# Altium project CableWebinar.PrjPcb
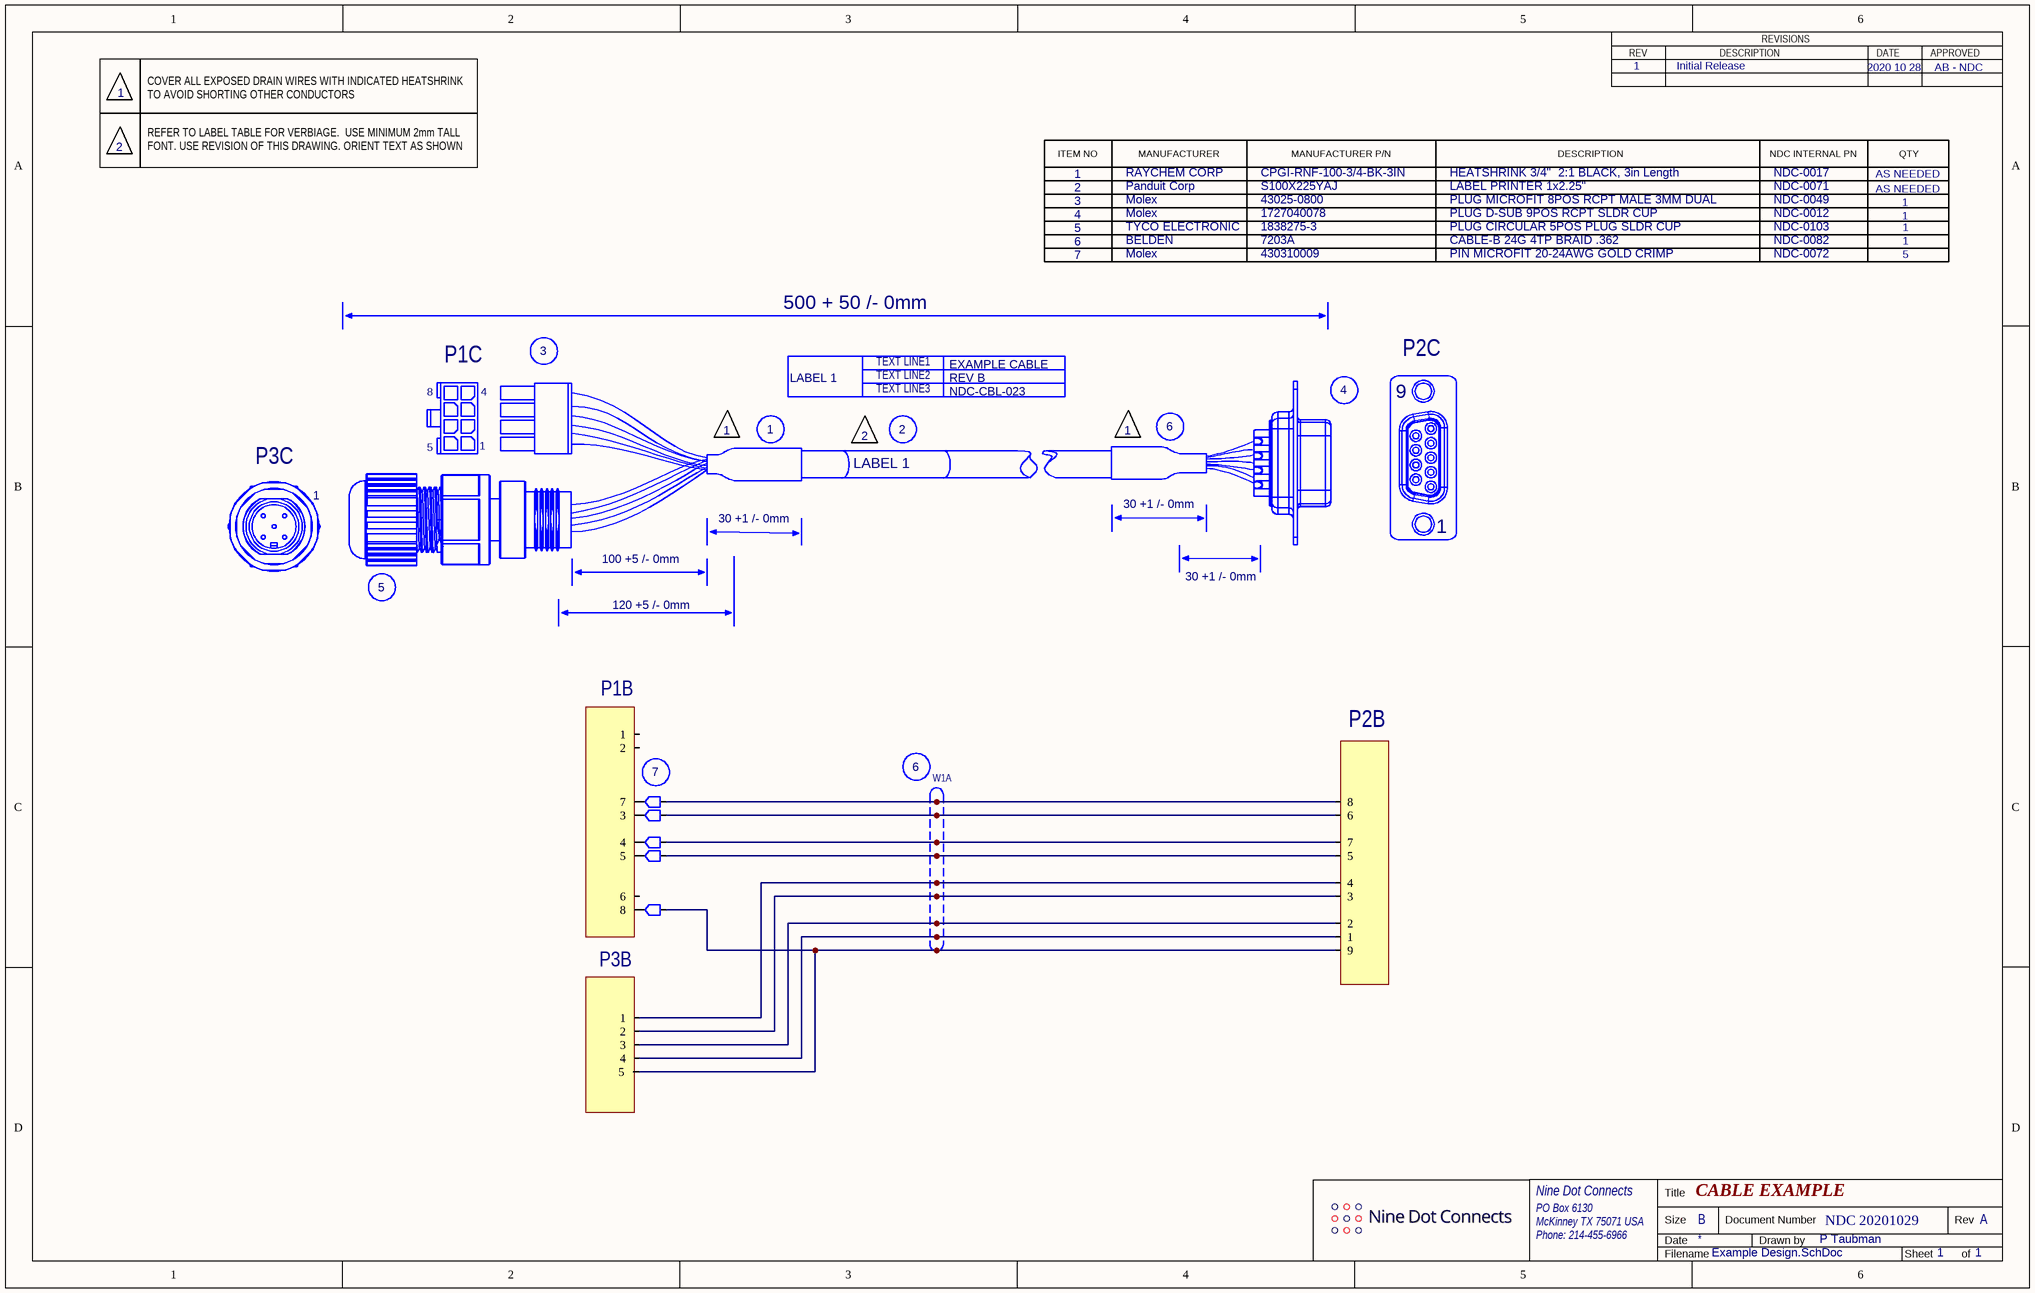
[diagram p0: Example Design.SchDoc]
1 sheet, 12 parts. Net scope: global (net labels, ports and power ports of the same name join across sheets).

## Sheet Example Design.SchDoc: CABLE EXAMPLE
size B; DrawnBy: P Taubman; Organization: Nine Dot Connects; Address1: PO Box 6130; Address2: McKinney TX 75071 USA; Address3: Phone: 214-455-6966; DocumentNumber: NDC 20201029; Revision: A; SheetNumber: 1; SheetTotal: 1

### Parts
HS1  HEATSHRINK 3/4"  2:1 BLACK, 3in Length  (value not drawn)  (parts A,B,C,D,E,F of 6)
HS2  HEATSHRINK 3/4"  2:1 BLACK, 3in Length  (value not drawn)  (parts A,B,D,E of 6)
LABEL1  LABEL PRINTER 1x2.25"  (value not drawn)  (parts A,B,C,D,E,F of 6)  (mechanical)
P1  PLUG MICROFIT 8POS RCPT MALE 3MM DUAL  (value not drawn)  (parts A,B,C,D,E,F of 6)
P2  PLUG D-SUB 9POS RCPT SLDR CUP  (value not drawn)  (parts A,B,C,D,E,F of 6)
P3  PLUG CIRCULAR 5POS PLUG SLDR CUP  (value not drawn)  (parts A,B,C,D,E,F of 6)
PIN1  PIN MICROFIT 20-24AWG GOLD CRIMP  (value not drawn)  (parts A,B,C,D of 4)
PIN2  PIN MICROFIT 20-24AWG GOLD CRIMP  (value not drawn)  (part A of 4)
PIN3  PIN MICROFIT 20-24AWG GOLD CRIMP  (value not drawn)  (part A of 4)
PIN4  PIN MICROFIT 20-24AWG GOLD CRIMP  (value not drawn)  (part A of 4)
PIN5  PIN MICROFIT 20-24AWG GOLD CRIMP  (value not drawn)  (part A of 4)
W1  CABLE-B,24G,4TP,BRAID,.362  (value not drawn)  (parts A,B,C,D of 4)

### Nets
NetP1_3: P1.3 PIN2.1
NetP1_4: P1.4 PIN3.1
NetP1_5: P1.5 PIN4.1
NetP1_7: P1.7 PIN1.1
NetP1_8: P1.8 PIN5.1
NetP2_1: P2.1 P3.4 W1.8(WHITE4)
NetP2_2: P2.2 P3.3 W1.7(ORANGE)
NetP2_3: P2.3 P3.2 W1.6(WHITE3)
NetP2_4: P2.4 P3.1 W1.5(BLUE)
NetP2_5: P2.5 PIN4.2 W1.4(WHITE2)
NetP2_6: P2.6 PIN2.2 W1.2(WHITE1)
NetP2_7: P2.7 PIN3.2 W1.3(GREEN)
NetP2_8: P2.8 PIN1.2 W1.1(BROWN)
NetP2_9: P2.9 P3.5 PIN5.2 W1.9(SHIELD)

Not connected (* = marked no-connect by the designer): P1 1 2 6

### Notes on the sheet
- 1
- Initial Release
- 2020 10 28
- AB - NDC
- ITEM NO
- MANUFACTURER
- MANUFACTURER P/N
- DESCRIPTION
- NDC INTERNAL PN
- QTY
- AS NEEDED
- 500 + 50 /- 0mm
- 5
- (near HS2) 30 +1 /- 0mm
- (near P3) 100 +5 /- 0mm
- (near HS1) 30 +1 /- 0mm
- 30 +1 /- 0mm
- 120 +5 /- 0mm

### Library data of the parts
HS1 = RayChem_CPGI-RNF-100-3/4-BK-3IN: Manufacturer: RAYCHEM CORP; BoM No: 1
HS2 = RayChem_CPGI-RNF-100-3/4-BK-3IN: Manufacturer: RAYCHEM CORP; BoM No: 6
LABEL1 = PanduitCorp_S100X225YAJ: Note Verbiage: REFER TO LABEL TABLE FOR LABELING INSTRUCTIONS.  USE MINIMUM 2mm TALL FONT. *  USE THE REVISION OF THIS DRAWING. ORIENT TEXT AS SHOWN.; Label Name: LABEL 1; BoM No: 2
P1 = Molex_43025-0800: Manufacturer: Molex; BoM No: 3; Wire Method: Solder
P2 = Molex_1727040078: Manufacturer: Molex; Plug Type: DSUB; Line Item: BoM#; Wire Method: Solder; BoM No: 4
P3 = TYCO_1838275-3: Manufacturer: TYCO ELECTRONIC; Wire Method: Solder; BoM No: 5
PIN1-PIN5 = Molex_430310009: Manufacturer: Molex; BoM No: 7
W1 = Belden_7203A: CABLE-B 24G 4TP BRAID .362; Manufacturer: BELDEN; Manufacturer PN: 7203A; BoM No: 6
